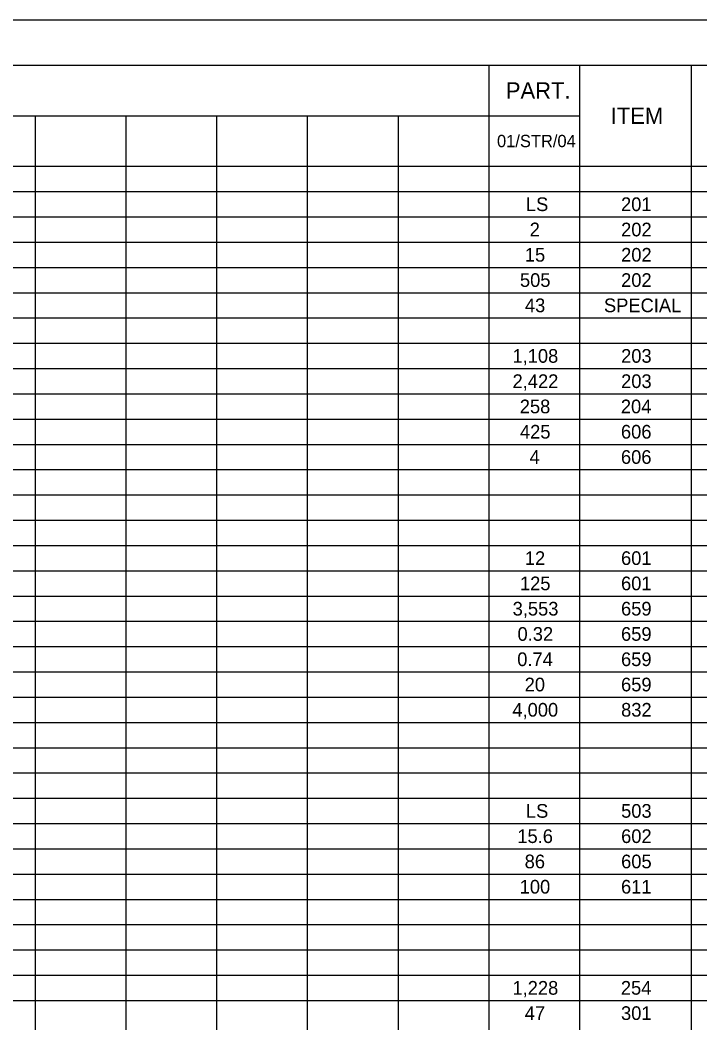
# Model space of a CAD drawing. Extents: x 0 to 34, y 0 to 22.
# Drawn here: x 9.37 to 16.9, y 10.89 to 22 of the extents above; entities that cross this region are included whole.
import ezdxf

# ---------------------------------------------------------------- set-up
doc = ezdxf.new("R2010")
doc.units = 0
for name, color, linetype in [('SH_Border', 7, 'Continuous'), ('SH_Cut_Line', 7, 'Continuous'), ('SH_Text', 7, 'Continuous')]:
    doc.layers.add(name, color=color, linetype=linetype)

msp = doc.modelspace()

# ---------------------------------------------------------------- linework, layer by layer
at = {"layer": 'SH_Border'}
msp.add_lwpolyline([(1.5, 21.5), (33.5, 21.5), (33.5, 0.5), (1.5, 0.5)], close=True, dxfattribs=at)
at = {"layer": 'SH_Cut_Line'}
msp.add_lwpolyline([(0, 0), (34, 0), (34, 22), (0, 22)], close=True, dxfattribs=at)
at = {"layer": 'SH_Text'}
for p, q in [((1.5, 21.5), (32, 21.5)), ((14.56, 21.5), (14.56, 0.5)), ((15.564, 21.5), (15.564, 0.5)), ((16.799, 21.5), (16.799, 0.5)), ((1.5, 20.94), (15.564, 20.94)), ((9.537, 20.94), (9.537, 0.5)), ((10.541, 20.94), (10.541, 0.5)), ((11.546, 20.94), (11.546, 0.5)), ((12.55, 20.94), (12.55, 0.5)), ((13.555, 20.94), (13.555, 0.5)), ((1.5, 20.38), (32, 20.38)), ((1.5, 20.1), (32, 20.1)), ((1.5, 19.82), (32, 19.82)), ((1.5, 19.54), (32, 19.54)), ((1.5, 19.26), (32, 19.26)), ((1.5, 18.98), (32, 18.98)), ((1.5, 18.7), (32, 18.7)), ((1.5, 18.42), (32, 18.42)), ((1.5, 18.14), (32, 18.14)), ((1.5, 17.86), (32, 17.86)), ((1.5, 17.58), (32, 17.58)), ((1.5, 17.3), (32, 17.3)), ((1.5, 17.02), (32, 17.02)), ((1.5, 16.74), (32, 16.74)), ((1.5, 16.46), (32, 16.46)), ((1.5, 16.18), (32, 16.18)), ((1.5, 15.9), (32, 15.9)), ((1.5, 15.62), (32, 15.62)), ((1.5, 15.34), (32, 15.34)), ((1.5, 15.06), (32, 15.06)), ((1.5, 14.78), (32, 14.78)), ((1.5, 14.5), (32, 14.5)), ((1.5, 14.22), (32, 14.22)), ((1.5, 13.94), (32, 13.94)), ((1.5, 13.66), (32, 13.66)), ((1.5, 13.38), (32, 13.38)), ((1.5, 13.1), (32, 13.1)), ((1.5, 12.82), (32, 12.82)), ((1.5, 12.54), (32, 12.54)), ((1.5, 12.26), (32, 12.26)), ((1.5, 11.98), (32, 11.98)), ((1.5, 11.7), (32, 11.7)), ((1.5, 11.42), (32, 11.42)), ((1.5, 11.14), (32, 11.14))]:
    msp.add_line(p, q, dxfattribs=at)

# ---------------------------------------------------------------- texts
for s, height, p in [('PART.', 0.1818, (14.749, 21.129)), ('ITEM', 0.1818, (15.91, 20.849)), ('01/STR/04', 0.1364, (14.651, 20.592)), ('LS', 0.1515, (14.971, 19.884)), ('201', 0.1515, (16.024, 19.884)), ('2', 0.152, (15.013, 19.604)), ('202', 0.1515, (16.025, 19.604)), ('15', 0.1515, (14.959, 19.324)), ('202', 0.1515, (16.025, 19.324)), ('505', 0.1515, (14.905, 19.044)), ('202', 0.1515, (16.025, 19.044)), ('43', 0.1515, (14.96, 18.764)), ('SPECIAL', 0.1515, (15.835, 18.764)), ('1,108', 0.1515, (14.822, 18.204)), ('203', 0.1515, (16.025, 18.204)), ('2,422', 0.1515, (14.823, 17.924)), ('203', 0.1515, (16.025, 17.924)), ('258', 0.1515, (14.903, 17.644)), ('204', 0.1515, (16.022, 17.644)), ('425', 0.1515, (14.905, 17.364)), ('606', 0.1515, (16.023, 17.364)), ('4', 0.152, (15.011, 17.084)), ('606', 0.1515, (16.023, 17.084)), ('12', 0.1515, (14.959, 15.964)), ('601', 0.1515, (16.024, 15.964)), ('125', 0.1515, (14.905, 15.684)), ('601', 0.1515, (16.024, 15.684)), ('3,553', 0.1515, (14.824, 15.404)), ('659', 0.1515, (16.024, 15.404)), ('0.32', 0.1515, (14.878, 15.124)), ('659', 0.1515, (16.024, 15.124)), ('0.74', 0.1515, (14.875, 14.844)), ('659', 0.1515, (16.024, 14.844)), ('20', 0.1515, (14.957, 14.564)), ('659', 0.1515, (16.024, 14.564)), ('4,000', 0.1515, (14.821, 14.284)), ('832', 0.1515, (16.025, 14.284)), ('LS', 0.1515, (14.971, 13.164)), ('503', 0.1515, (16.025, 13.164)), ('15.6', 0.1515, (14.876, 12.884)), ('602', 0.1515, (16.025, 12.884)), ('86', 0.1515, (14.957, 12.604)), ('605', 0.1515, (16.025, 12.604)), ('100', 0.1515, (14.902, 12.324)), ('611', 0.1515, (16.024, 12.324)), ('1,228', 0.1515, (14.822, 11.204)), ('254', 0.1515, (16.022, 11.204)), ('47', 0.1515, (14.958, 10.924)), ('301', 0.1515, (16.024, 10.924))]:
    msp.add_text(s, height=height, dxfattribs=at).set_placement(p)

doc.saveas('drawing.dxf')
